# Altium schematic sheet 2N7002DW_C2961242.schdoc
size 127 x 101 mm
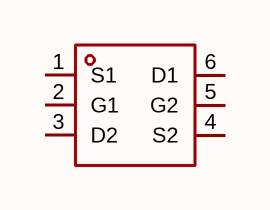
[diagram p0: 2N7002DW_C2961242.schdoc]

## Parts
Q?  2n7002dw_c2961242  [SC70-6_L2.1-W1.3-P0.65-LS2.3-BL]  (value not drawn)

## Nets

Not connected (* = marked no-connect by the designer): Q? 1(S1) 2(G1) 3(D2) 4(S2) 5(G2) 6(D1)

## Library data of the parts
Q? = 2n7002dw_c2961242: 数量:2个N沟道;漏源电压(Vdss):60V;连续漏极电流(Id):115mA;导通电阻(RDS(on)):7Ω@5V;耗散功率(Pd):150mW;阈值电压(Vgs(th)):2.5V;; Manufacturer: CJ(江苏长电/长晶); AddInBom: yes; ModelId: da3ee423e6884510a60d538ff097d4a3; ModelTransform: 82.677,90.551,0,0,0,0,0,0,0; Number: 2个N沟道; Drain to Source Voltage: 60V; Current - Continuous Drain(Id): 115mA; RDS(on): 7Ω@5V; Pd - Power Dissipation: 150mW; Gate Threshold Voltage (Vgs(th)): 2.5V; Input Capacitance(Ciss): 50pF; Reverse Transfer Capacitance (Crss@Vds): 5pF; Type: N沟道; Output Capacitance(Coss): 25pF; Vgs: ±20V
